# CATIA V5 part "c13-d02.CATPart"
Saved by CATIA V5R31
Part number: Part1
Bounding box of the stored display mesh (mm): x -33 to 33, y -200.819 to 48, z -35 to 35
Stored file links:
  D:\PROJECTS\Project 2021\US EDITION\CATIA V5 6R 2021\Resources\Part Files\c13_catia_v5_6r2021_prt\c13_catia_v5-6r2021_figr_13-17\c13-d02.CATPart
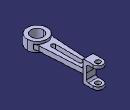
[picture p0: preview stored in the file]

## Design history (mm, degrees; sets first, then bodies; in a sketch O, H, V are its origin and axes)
Body1 (main body)
  Sketch1 on yz-plane, origin (0, 0, 0), H (0, 1, 0), V (0, 0, 1)
    line L1 (0, 0) -> (0, -35)
    point P1 (0, -35)
    line L2 (0, -35) -> (48, -35)
    point P2 (48, -35)
    line L3 (48, -35) -> (48, -25)
    point P3 (48, -25)
    line L4 (48, -25) -> (10, -25)
    point P4 (10, -25)
    line L5 (10, -25) -> (10, 0)
    point P5 (10, 0)
    point P6 (0, 0)
    point P7 (0, 0)
    point P8 (0, 35)
    point P9 (48, 35)
    point P10 (48, 25)
    point P11 (10, 25)
    point P12 (10, 0)
    point P13 (0, 0)
    line L6 (0, 0) -> (0, 35)
    line L7 (0, 35) -> (48, 35)
    line L8 (48, 35) -> (48, 25)
    line L9 (48, 25) -> (10, 25)
    line L10 (10, 25) -> (10, 0)
    length L8 = 10
    distance P3 L9 = 50
    length L2 = 48
    distance L10 L6 = 10
    vertical: L1 V, L3 V, L5 V
    horizontal: L2 H, L4 H
    symmetry: O P7 H, P1 P8 H, P2 P9 H, P3 P10 H, P4 P11 H, P5 P12 H, P6 P13 H, L1 L6 H, L2 L7 H, L3 L8 H, L4 L9 H, L5 L10 H
    coincidence: P13 P7, P12 P5, P6 P7
  Pad1: profile Sketch1, direction (1, 0, 0), length 16, mirrored extent
  Sketch2 on xy-plane, origin (0, 0, 0), H (1, 0, 0), V (0, 1, 0)
    circle A1 centre (0, -168) radius 33
    point P1 (0, -168)
    circle A2 centre (0, -168) radius 20
    distance P1 H = 168
    radius A1 = 33
    radius A2 = 20
    coincidence: P1 V
  Pad2: profile Sketch2, direction (0, 0, 1), length 16, mirrored extent
  Sketch3 on xy-plane, origin (0, 0, 0), H (1, 0, 0), V (0, 1, 0)
    line L1 (-16, 0) -> (-25, -146.4593)
    point P1 (-16, 0)
    point P2 (-25, -146.4593)
    line L2 (16, 0) -> (25, -146.4593)
    point P3 (16, 0)
    point P4 (25, -146.4593)
    reference projected line E1 (16, 48) -> (16, 0) from edge [face of Pad1 | face of Pad1]
    reference projected line E2 (-16, 48) -> (-16, 0) from edge [face of Pad1 | face of Pad1]
    projected circle E3 centre (0, -168) radius 33 from edge [face of Pad2 | face of Pad2]
    projected arc E4 centre (0, -168) radius 33 from (25, -146.4593) to (-25, -146.4593) ccw from edge [face of Pad2 | face of Pad2]
    line L3 (-16, 0) -> (16, 0)
    distance P4 P2 H = 50
    coincidence: P1 H, P3 H, P3 E1, P1 E2, P2 E3, P4 E3
    symmetry: P4 P2 V
    horizontal: L3 H
  Pad3: profile Sketch3, direction (0, 0, 1), length 8, mirrored extent
  Fillet1: radius 6, on edge [face of Pad1 | face of Pad3]; edge [face of Pad3 | face of Pad1]; edge [face of Pad1 | face of Pad1] (x2)
  Fillet2: radius 30, on edge [face of Pad3 | face of Pad2]; edge [face of Pad2 | face of Pad3]
  TritangentFillet1: Face1 face of Pad1, Face2 face of Pad1, RemoveFace face of Pad1
  TritangentFillet2: Face1 face of Pad1, Face2 face of Pad1, RemoveFace face of Pad1
  Sketch4 on face of Pad1, origin (2.8418, 32, 35), H (1, 0, 0), V (0, 1, 0)
    point P1 (-2.8418, 0)
    reference projected arc E1 centre (-2.8418, 0) radius 16 from (13.1582, 0) to (-18.8418, 0) ccw from edge [face of Pad1 | face of TritangentFillet1]
    concentricity: P1 E1
  Hole1: placed by Sketch4, at (0, 32, 35) direction (0, 0, -1), diameter 16, through (limit type 3)
  Sketch5 on face of Pad3, origin (0, 0, 8), H (1, 0, 0), V (0, 1, 0)
    construction line L1 (0, -25) -> (0, -115)
    point P1 (0, -25)
    line L2 (7, -25) -> (7, -115)
    line L3 (-7, -115) -> (-7, -25)
    arc A1 centre (0, -115) radius 7 from (7, -115) to (-7, -115) cw
    arc A2 centre (0, -25) radius 7 from (-7, -25) to (7, -25) cw
    distance P1 H = 25
    length L1 = 90
    radius A1 = 7
    coincidence: P1 V
    vertical: L1 V
    tangency: A1 L2, A2 L2, A1 L3, A2 L3
    parallelism: L1 L2
  Pocket1: profile Sketch5, direction (0, 0, -1), through (limit type 3)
